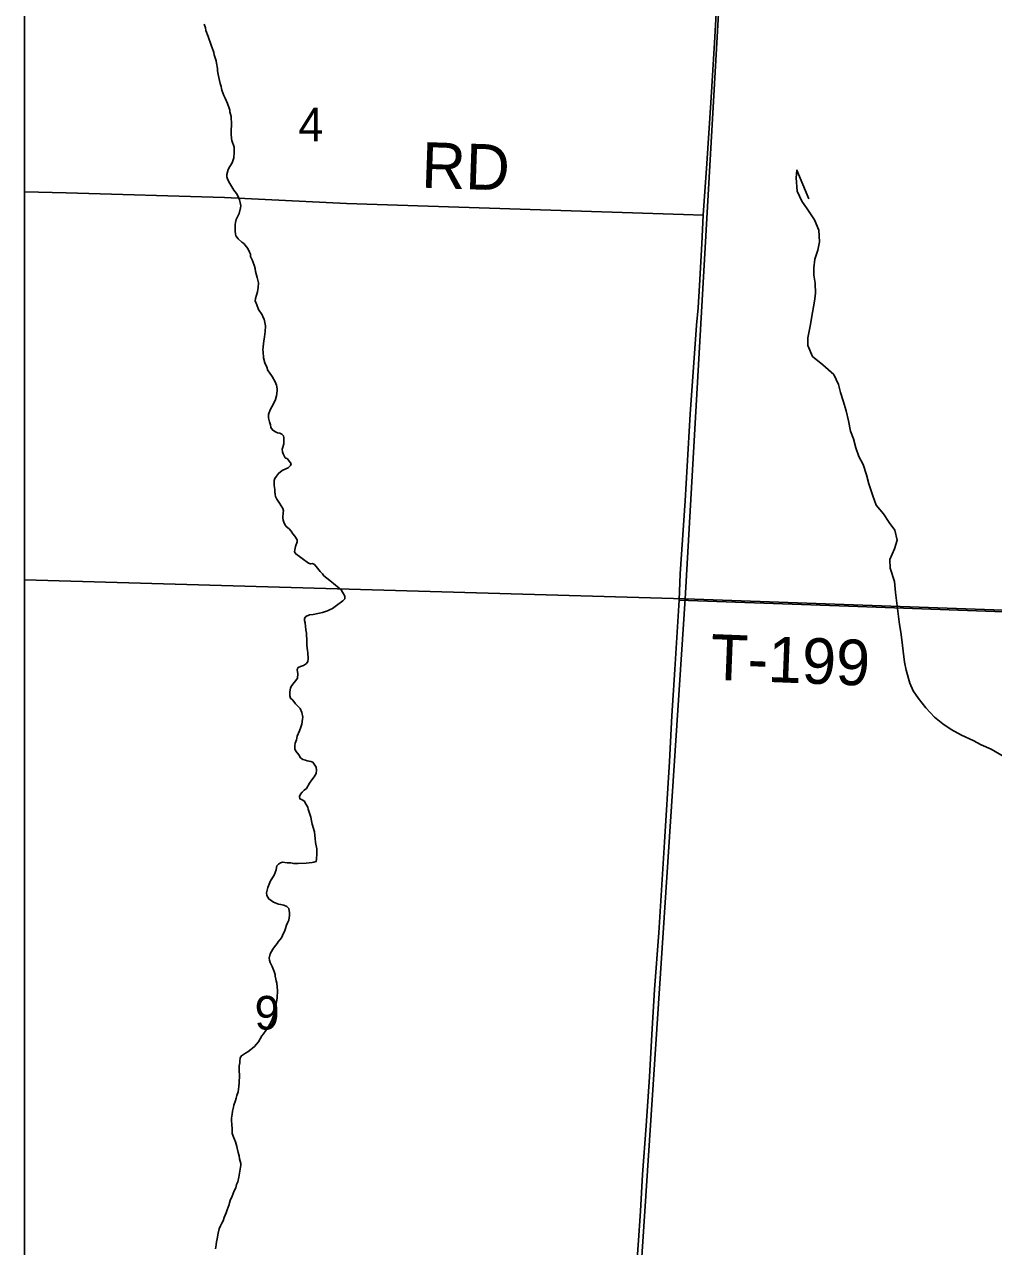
# Model space of a CAD drawing. Extents: x 0 to 34, y 0 to 22.
# Drawn here: x 2.1 to 3.306, y 15.984 to 17.505 of the extents above; entities that cross this region are included whole.
import ezdxf

# ---------------------------------------------------------------- set-up
doc = ezdxf.new("R2010")
doc.units = 0
for name, color, linetype in [('Default', 7, 'Continuous'), ('GM_X_Minor_River', 7, 'Continuous'), ('GM_X_Section', 7, 'Continuous'), ('GM_X_Section_Text', 7, 'Continuous'), ('GM_X_State_Route', 7, 'Continuous'), ('GM_X_Township_Road', 7, 'Continuous'), ('GM_X_Township_Road_Text', 7, 'Continuous'), ('SH_Data', 7, 'Continuous')]:
    doc.layers.add(name, color=color, linetype=linetype)

msp = doc.modelspace()

# ---------------------------------------------------------------- linework, layer by layer
at = {"layer": 'Default'}
msp.add_lwpolyline([(5.0396, 17.6997), (4.98, 17.7015), (4.9045, 17.7039), (4.763, 17.7084), (4.6735, 17.7102), (4.6237, 17.7121), (4.506, 17.7155), (4.4203, 17.718), (4.2769, 17.7222), (4.1969, 17.7246), (4.1354, 17.7264), (4.1238, 17.7269), (4.1165, 17.7286), (3.9904, 17.7296), (3.7662, 17.7368), (3.4544, 17.7458), (3.1037, 17.7609), (2.976, 17.7664), (2.8305, 17.7727), (2.1, 17.8044), (2.1, 14.1), (5.898, 14.1)], dxfattribs=at)
for points in [[(2.1, 17.8037), (2.1, 16.814), (2.9224, 16.7901), (2.9781, 17.7672)], [(2.1, 16.814), (2.1, 15.7743), (2.854, 15.751), (2.9224, 16.7901)]]:
    msp.add_lwpolyline(points, close=True, dxfattribs=at)
at = {"layer": 'GM_X_Minor_River'}
for points in [[(2.3404, 17.4504), (2.339, 17.4569), (2.3387, 17.46), (2.3362, 17.4676), (2.3359, 17.4703), (2.3337, 17.476), (2.333, 17.4783), (2.3316, 17.4818), (2.3294, 17.4879), (2.3287, 17.4902), (2.3259, 17.4979), (2.3252, 17.5009), (2.3238, 17.5055)], [(2.4225, 16.993), (2.4203, 16.9953), (2.4181, 16.9965), (2.415, 16.997), (2.4116, 16.9986), (2.4086, 17.0005), (2.4068, 17.0036), (2.4061, 17.0067), (2.4051, 17.0105), (2.4037, 17.0158), (2.4038, 17.0196), (2.4058, 17.0257), (2.4078, 17.0294), (2.4102, 17.0332), (2.4126, 17.0384), (2.4138, 17.0429), (2.4147, 17.0494), (2.4144, 17.0517), (2.4137, 17.0562), (2.4123, 17.0605), (2.4083, 17.067), (2.4046, 17.0724), (2.4031, 17.0747), (2.4017, 17.0786), (2.3992, 17.084), (2.3974, 17.0905), (2.3972, 17.0977), (2.3969, 17.1003), (2.397, 17.1034), (2.3975, 17.1083), (2.3983, 17.114), (2.3988, 17.1162), (2.3992, 17.12), (2.3997, 17.1227), (2.3999, 17.1303), (2.3985, 17.1383), (2.3971, 17.1406), (2.396, 17.144), (2.3912, 17.1506), (2.3894, 17.1564), (2.3873, 17.1614), (2.3877, 17.164), (2.3902, 17.1723), (2.3911, 17.178), (2.3912, 17.1837), (2.3899, 17.1905), (2.3877, 17.1978), (2.3874, 17.2016), (2.386, 17.2058), (2.3835, 17.2123), (2.3813, 17.2166), (2.3814, 17.2192), (2.3803, 17.2219), (2.3781, 17.2265), (2.373, 17.2327), (2.3707, 17.2343), (2.3659, 17.2386), (2.3633, 17.2421), (2.3626, 17.2448), (2.3623, 17.2474), (2.3625, 17.2562), (2.3629, 17.2588), (2.3634, 17.2626), (2.3674, 17.2701), (2.369, 17.2769), (2.3695, 17.2795), (2.3684, 17.2837), (2.3677, 17.2868), (2.3667, 17.2895), (2.3638, 17.2949), (2.3608, 17.2991), (2.3557, 17.3072), (2.3531, 17.3119), (2.3521, 17.3157), (2.3521, 17.3187), (2.3538, 17.3248), (2.3558, 17.3285), (2.3586, 17.333), (2.3606, 17.3394), (2.3611, 17.3458), (2.3612, 17.3485), (2.3609, 17.3527), (2.3581, 17.3607), (2.3577, 17.363), (2.3575, 17.3691), (2.3578, 17.3843), (2.3575, 17.387), (2.3572, 17.3908), (2.3558, 17.3965), (2.3555, 17.3988), (2.3548, 17.4011), (2.3527, 17.4068), (2.3498, 17.4137), (2.3483, 17.4168), (2.3458, 17.4233), (2.3451, 17.4256), (2.3448, 17.4279), (2.3437, 17.4317), (2.341, 17.4432), (2.3403, 17.4474), (2.3404, 17.4504)], [(3.0897, 17.2346), (3.0888, 17.2494), (3.0837, 17.2621), (3.0745, 17.2759), (3.0678, 17.2855), (3.062, 17.2978), (3.0608, 17.3145), (3.0617, 17.324), (3.0766, 17.2884)], [(3.3182, 16.5944), (3.3035, 16.603), (3.2911, 16.6085), (3.281, 16.614), (3.2666, 16.6204), (3.2535, 16.6278), (3.2434, 16.6348), (3.2329, 16.643), (3.2221, 16.6546), (3.2128, 16.6661), (3.2062, 16.6757), (3.2022, 16.6853), (3.1975, 16.7017), (3.1955, 16.7116), (3.1938, 16.7253), (3.1922, 16.7394), (3.1908, 16.7489), (3.1895, 16.7585), (3.1878, 16.7718), (3.1858, 16.7847), (3.1845, 16.798), (3.1832, 16.8117), (3.1775, 16.8286), (3.1773, 16.8392), (3.1829, 16.8524), (3.1865, 16.8633), (3.1833, 16.8756), (3.1766, 16.8855), (3.1696, 16.8959), (3.1603, 16.9071), (3.156, 16.9186), (3.1513, 16.9335), (3.1481, 16.9445), (3.1442, 16.9575), (3.1387, 16.9675), (3.1351, 16.9782), (3.1319, 16.9893), (3.1282, 16.9992), (3.1258, 17.0118), (3.123, 17.0244), (3.1191, 17.0366), (3.1158, 17.0473), (3.1134, 17.0572), (3.1075, 17.0695), (3.0937, 17.0815), (3.081, 17.092), (3.0752, 17.1057), (3.0753, 17.1152), (3.0779, 17.1296), (3.0809, 17.1466), (3.0834, 17.1607), (3.0847, 17.1705), (3.0842, 17.1834), (3.0825, 17.193), (3.0826, 17.2024), (3.084, 17.2131), (3.0876, 17.2244), (3.0897, 17.2346)], [(2.4463, 16.6406), (2.4464, 16.6429), (2.4454, 16.6486), (2.4432, 16.6536), (2.4376, 16.6595), (2.4339, 16.6641), (2.4313, 16.6665), (2.4303, 16.6695), (2.4304, 16.6745), (2.4312, 16.679), (2.432, 16.6813), (2.434, 16.6842), (2.4379, 16.6887), (2.4399, 16.6917), (2.4404, 16.697), (2.4394, 16.7023), (2.4406, 16.705), (2.4436, 16.706), (2.4475, 16.7075), (2.4513, 16.71), (2.4529, 16.7123), (2.4534, 16.7157), (2.4528, 16.7233), (2.4525, 16.7259), (2.4515, 16.7321), (2.4516, 16.737), (2.4511, 16.7476), (2.4504, 16.7515), (2.4495, 16.7606), (2.4488, 16.7633), (2.4488, 16.7659), (2.4504, 16.7682), (2.455, 16.7703), (2.4596, 16.771), (2.4711, 16.7733), (2.4772, 16.7755), (2.4799, 16.7765), (2.4834, 16.7784), (2.4884, 16.782), (2.4965, 16.7879), (2.4988, 16.7901), (2.4989, 16.7935), (2.4942, 16.8016), (2.4912, 16.804), (2.4871, 16.8075), (2.48, 16.813), (2.4729, 16.8189), (2.471, 16.8216), (2.4681, 16.8243), (2.4647, 16.8286), (2.461, 16.8329), (2.4584, 16.8341), (2.4561, 16.8337), (2.4535, 16.8346), (2.4456, 16.8405), (2.4423, 16.8432), (2.4378, 16.8463), (2.4363, 16.849), (2.4364, 16.8513), (2.4376, 16.8555), (2.4393, 16.8611), (2.4397, 16.8638), (2.4368, 16.8684), (2.4342, 16.8711), (2.432, 16.8746), (2.4294, 16.8773), (2.426, 16.8804), (2.4242, 16.8828), (2.4231, 16.8858), (2.422, 16.8881), (2.4217, 16.8912), (2.4219, 16.8976), (2.4223, 16.8999), (2.4216, 16.9026), (2.4176, 16.9095), (2.4143, 16.9145), (2.4124, 16.9176), (2.4121, 16.9203), (2.4118, 16.9241), (2.4115, 16.9264), (2.4108, 16.9313), (2.411, 16.9378), (2.4118, 16.9401), (2.4138, 16.943), (2.4161, 16.9464), (2.4208, 16.9501), (2.4254, 16.9523), (2.4281, 16.9533), (2.4312, 16.9563), (2.432, 16.9585), (2.4276, 16.9644), (2.4246, 16.9659), (2.4235, 16.9683), (2.422, 16.9709), (2.4213, 16.9732), (2.421, 16.9767), (2.4215, 16.9793), (2.4227, 16.9831), (2.4231, 16.9861), (2.4229, 16.9907), (2.4225, 16.993)], [(2.4143, 16.2908), (2.4147, 16.2938), (2.4149, 16.3029), (2.414, 16.3117), (2.4133, 16.3148), (2.413, 16.317), (2.4123, 16.3205), (2.412, 16.3228), (2.4109, 16.3266), (2.4084, 16.3327), (2.4058, 16.3377), (2.4051, 16.3404), (2.4048, 16.3431), (2.4057, 16.3484), (2.4093, 16.3544), (2.4112, 16.357), (2.4144, 16.3611), (2.4159, 16.3633), (2.4199, 16.3685), (2.4211, 16.3712), (2.4242, 16.3775), (2.4251, 16.3798), (2.4263, 16.384), (2.4279, 16.3877), (2.4291, 16.3903), (2.43, 16.396), (2.4301, 16.3994), (2.4291, 16.4048), (2.4265, 16.4075), (2.4231, 16.4091), (2.4189, 16.41), (2.4163, 16.4104), (2.414, 16.4112), (2.4102, 16.4128), (2.4042, 16.4168), (2.4017, 16.421), (2.4014, 16.4245), (2.403, 16.4309), (2.4039, 16.4331), (2.4063, 16.4392), (2.411, 16.4463), (2.4134, 16.453), (2.4139, 16.4557), (2.4143, 16.458), (2.4163, 16.4602), (2.4186, 16.4616), (2.4213, 16.4623), (2.427, 16.4618), (2.4315, 16.4617), (2.4349, 16.4609), (2.4406, 16.4607), (2.4505, 16.4612), (2.4582, 16.4622), (2.4604, 16.4625), (2.4631, 16.4632), (2.4636, 16.4662), (2.4641, 16.4727), (2.4638, 16.4765), (2.4639, 16.4791), (2.4625, 16.4868), (2.4619, 16.4921), (2.4616, 16.4955), (2.4609, 16.5001), (2.4581, 16.51), (2.4574, 16.5139), (2.4564, 16.5184), (2.4532, 16.5284), (2.4529, 16.5311), (2.45, 16.5357), (2.4485, 16.5384), (2.4451, 16.5404), (2.4429, 16.5412), (2.4422, 16.5443), (2.4438, 16.5473), (2.4457, 16.5495), (2.4481, 16.5521), (2.4512, 16.5543), (2.4547, 16.561), (2.4579, 16.5651), (2.4606, 16.5689), (2.463, 16.573), (2.4635, 16.5771), (2.4632, 16.5806), (2.4588, 16.5868), (2.4565, 16.588), (2.4542, 16.5884), (2.452, 16.5885), (2.4497, 16.5893), (2.4467, 16.5901), (2.4437, 16.5925), (2.4415, 16.5959), (2.4378, 16.6006), (2.4367, 16.6036), (2.4364, 16.6075), (2.4369, 16.6105), (2.4385, 16.6146), (2.4394, 16.6195), (2.4426, 16.6259), (2.4442, 16.6304), (2.4454, 16.6342), (2.4463, 16.6406)], [(2.3379, 15.9812), (2.3388, 15.9861), (2.3392, 15.9899), (2.3401, 15.9936), (2.341, 16.0005), (2.3426, 16.0061), (2.3439, 16.0099), (2.3459, 16.0133), (2.3474, 16.0159), (2.3487, 16.02), (2.3511, 16.026), (2.3523, 16.0298), (2.3548, 16.0362), (2.3552, 16.0385), (2.356, 16.0415), (2.3584, 16.0468), (2.36, 16.0501), (2.3609, 16.0532), (2.3632, 16.0573), (2.3641, 16.0611), (2.3657, 16.0644), (2.367, 16.0705), (2.3683, 16.0777), (2.3692, 16.0852), (2.3692, 16.0875), (2.3679, 16.0933), (2.3672, 16.0971), (2.3661, 16.1009), (2.3647, 16.1063), (2.3644, 16.1085), (2.3626, 16.1143), (2.3605, 16.1193), (2.3587, 16.1246), (2.3584, 16.1292), (2.3582, 16.1372), (2.3579, 16.1395), (2.3576, 16.1437), (2.3585, 16.1486), (2.359, 16.1524), (2.3602, 16.1577), (2.3607, 16.1599), (2.3627, 16.166), (2.3635, 16.1686), (2.3644, 16.172), (2.366, 16.1765), (2.3669, 16.1833), (2.3674, 16.1879), (2.3676, 16.197), (2.3674, 16.2031), (2.3671, 16.2065), (2.3675, 16.2091), (2.368, 16.2125), (2.368, 16.2148), (2.3685, 16.219), (2.3701, 16.2216), (2.3751, 16.2249), (2.3782, 16.2264), (2.3817, 16.2293), (2.384, 16.2308), (2.3863, 16.233), (2.3914, 16.2389), (2.3957, 16.2464), (2.3977, 16.249), (2.4032, 16.2569), (2.4076, 16.2644), (2.4088, 16.2678), (2.4112, 16.2753), (2.4121, 16.2798), (2.4125, 16.2825), (2.4143, 16.2908)]]:
    msp.add_lwpolyline(points, dxfattribs=at)
at = {"layer": 'GM_X_Section'}
for points in [[(2.9781, 17.7672), (3.9286, 17.7304), (3.904, 16.7335), (3.4696, 16.7535), (3.47, 16.7707), (2.9224, 16.7901)], [(2.9224, 16.7901), (3.47, 16.7707), (3.4696, 16.7535), (3.904, 16.7335), (3.8671, 15.713), (2.854, 15.751)]]:
    msp.add_lwpolyline(points, close=True, dxfattribs=at)
at = {"layer": 'GM_X_State_Route'}
msp.add_lwpolyline([(2.8602, 15.9354), (2.8638, 15.9857), (2.8668, 16.0281), (2.8695, 16.0738), (2.8739, 16.1343), (2.8779, 16.1954), (2.8808, 16.2481), (2.8845, 16.3039), (2.8898, 16.3746), (2.8967, 16.4873), (2.9029, 16.5879), (2.906, 16.6448), (2.9096, 16.7025), (2.9149, 16.7888), (2.9164, 16.8215), (2.9224, 16.9121), (2.9289, 17.0203), (2.9368, 17.1311), (2.9385, 17.1527), (2.9404, 17.1804), (2.9434, 17.2324), (2.9451, 17.2677), (2.9496, 17.3323), (2.9543, 17.4078), (2.9589, 17.4823), (2.9635, 17.5634)], dxfattribs=at)
at = {"layer": 'GM_X_Township_Road'}
for points in [[(2.1, 17.2971), (2.1519, 17.2956), (2.3489, 17.29), (2.501, 17.2826), (2.9203, 17.2688), (2.9451, 17.2677)], [(2.9149, 16.7888), (3.1374, 16.7808), (3.365, 16.7726), (3.3847, 16.7722), (3.3998, 16.7719), (3.4128, 16.7769)]]:
    msp.add_lwpolyline(points, dxfattribs=at)
at = {"layer": 'SH_Data'}
msp.add_line((2.1, 20.9), (2.1, 14.1), dxfattribs=at)

# ---------------------------------------------------------------- texts
at = {"layer": 'GM_X_Section_Text'}
for s, p in [('4', (2.4411, 17.3599)), ('9', (2.3865, 16.2541))]:
    msp.add_text(s, height=0.0419, rotation=0, dxfattribs=at).set_placement(p)
at = {"layer": 'GM_X_Township_Road_Text'}
for s, rotation, p in [('RD', 358.0243, (2.5935, 17.3022)), ('T-199', 357.7544, (2.9531, 16.6897))]:
    msp.add_text(s, height=0.05682, rotation=rotation, dxfattribs=at).set_placement(p)

doc.saveas('drawing.dxf')
